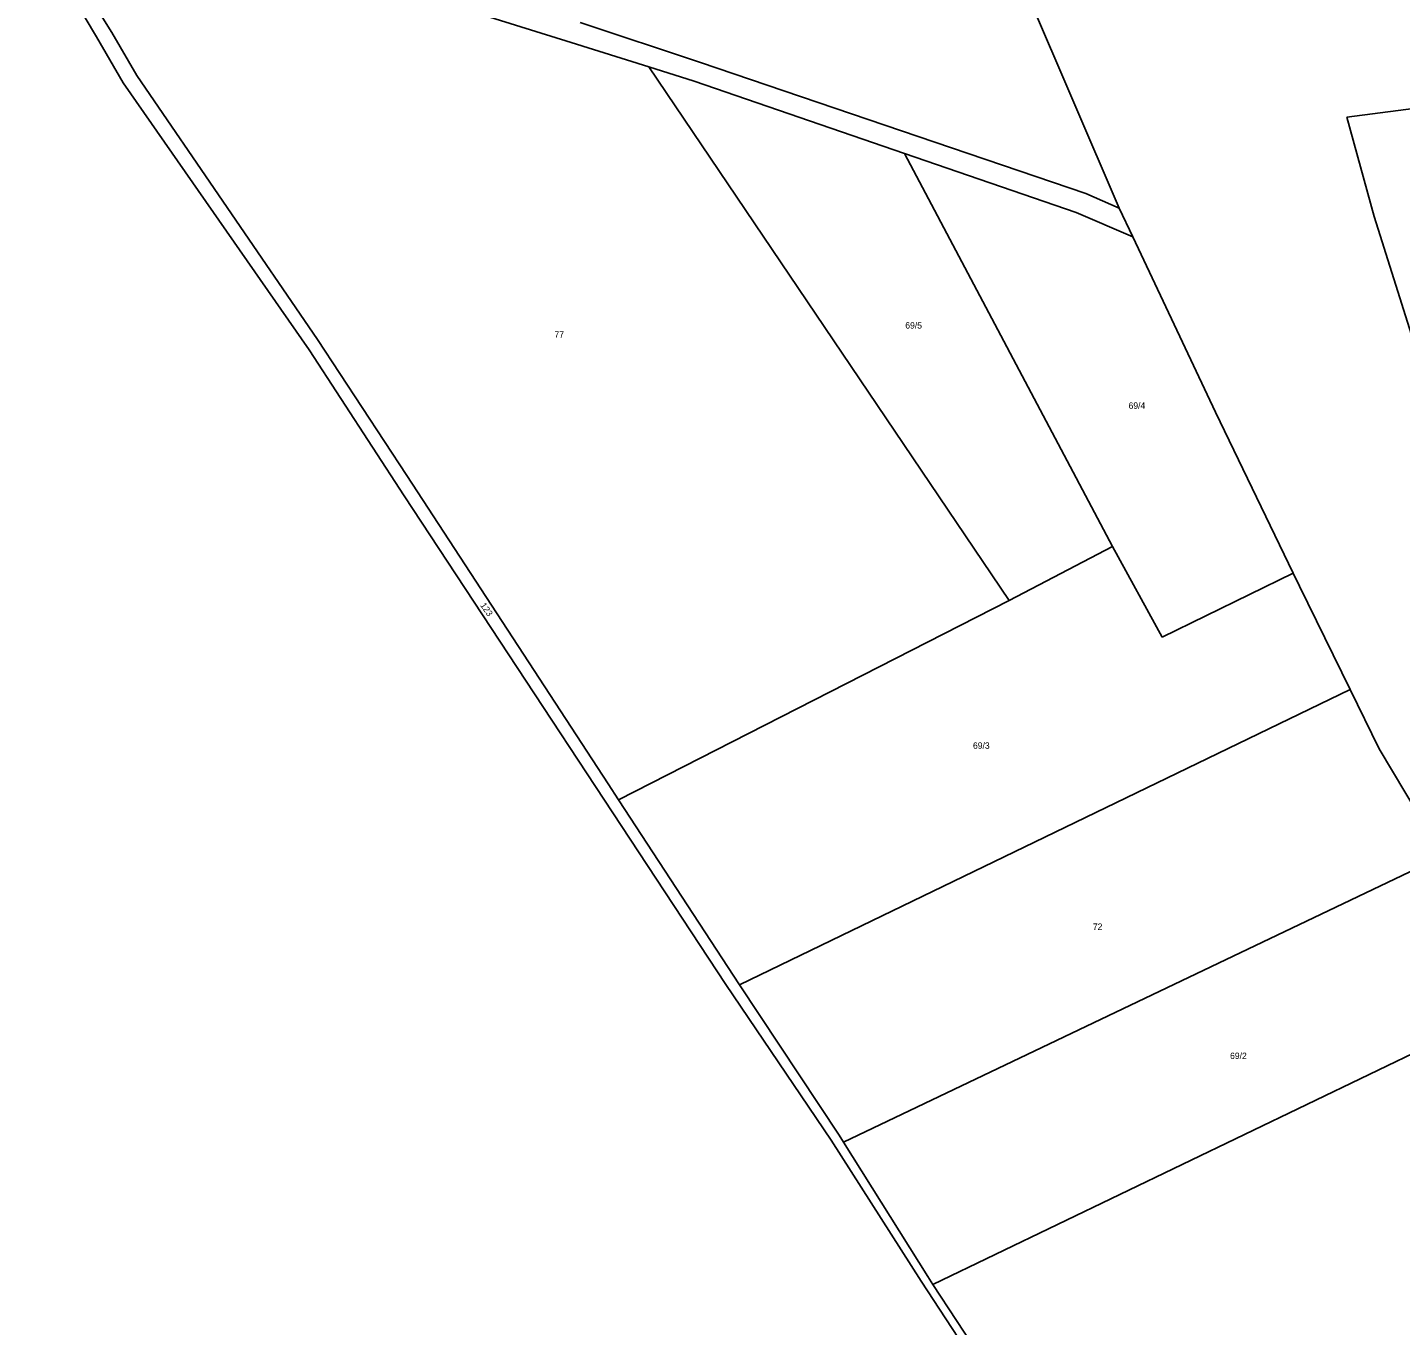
# Model space of a CAD drawing. Extents: x -752343 to -750336, y -1035826 to -1033329.
# Drawn here: x -750977.4 to -750613.5, y -1035442.9 to -1035099 of the extents above; entities that cross this region are included whole.
import ezdxf

# ---------------------------------------------------------------- set-up
doc = ezdxf.new("R2010")
doc.units = 0
doc.layers.add('KN_HRANICE', color=7, linetype='Continuous')
doc.layers.add('KN_PARCELY', color=7, linetype='Continuous')

msp = doc.modelspace()

# ---------------------------------------------------------------- linework, layer by layer
at = {"layer": 'KN_HRANICE'}
for p, q in [((-750977.4, -1035070.62), (-750959.13, -1035101.47)), ((-750974.34, -1035069.13), (-750955.05, -1035100.37)), ((-750892.88, -1035084.41), (-750833.35, -1035102.98)), ((-750713.44, -1035087.79), (-750688.06, -1035146.89)), ((-750830.94, -1035097.68), (-750799.07, -1035108.28)), ((-750955.05, -1035100.37), (-750948.45, -1035111.72)), ((-750959.13, -1035101.47), (-750952.01, -1035113.65)), ((-750833.35, -1035102.98), (-750812.7, -1035109.45)), ((-750799.07, -1035108.28), (-750696.95, -1035143.05)), ((-750948.45, -1035111.72), (-750900.52, -1035181.7)), ((-750717.21, -1035250.8), (-750812.7, -1035109.45)), ((-750812.7, -1035109.45), (-750800.69, -1035113.22)), ((-750952.01, -1035113.65), (-750902.74, -1035184.42)), ((-750744.96, -1035132.4), (-750800.69, -1035113.22)), ((-750627.75, -1035122.82), (-750580.87, -1035116.68)), ((-750620.53, -1035149.1), (-750627.75, -1035122.82)), ((-750689.89, -1035236.52), (-750744.96, -1035132.4)), ((-750699.48, -1035148.05), (-750744.96, -1035132.4)), ((-750696.95, -1035143.05), (-750688.06, -1035146.89)), ((-750684.47, -1035154.53), (-750699.48, -1035148.05)), ((-750688.06, -1035146.89), (-750684.47, -1035154.53)), ((-750610.6, -1035180.44), (-750620.53, -1035149.1)), ((-750684.47, -1035154.53), (-750662.59, -1035200.92)), ((-750902.74, -1035184.42), (-750877.61, -1035223.09)), ((-750900.52, -1035181.7), (-750876.9, -1035217.73)), ((-750662.59, -1035200.92), (-750641.95, -1035243.61)), ((-750876.9, -1035217.73), (-750823.55, -1035299.39)), ((-750877.61, -1035223.09), (-750792.36, -1035352.54)), ((-750689.89, -1035236.52), (-750717.21, -1035250.8)), ((-750676.68, -1035260.56), (-750689.89, -1035236.52)), ((-750641.95, -1035243.61), (-750676.68, -1035260.56)), ((-750641.95, -1035243.61), (-750640.28, -1035247.07)), ((-750640.28, -1035247.07), (-750626.88, -1035274.39)), ((-750717.21, -1035250.8), (-750820.76, -1035303.65)), ((-750626.88, -1035274.39), (-750788.73, -1035352.67)), ((-750626.88, -1035274.39), (-750619.19, -1035290.09)), ((-750619.19, -1035290.09), (-750602.3, -1035318.55)), ((-750823.55, -1035299.39), (-750820.76, -1035303.65)), ((-750820.76, -1035303.65), (-750788.73, -1035352.67)), ((-750761.16, -1035394.35), (-750602.3, -1035318.55)), ((-750553.02, -1035343.26), (-750737.45, -1035432.01)), ((-750792.36, -1035352.54), (-750764.38, -1035393.81)), ((-750788.73, -1035352.67), (-750762.33, -1035392.48)), ((-750764.38, -1035393.81), (-750740.57, -1035431.12)), ((-750762.33, -1035392.48), (-750761.16, -1035394.35)), ((-750761.16, -1035394.35), (-750738.8, -1035429.95)), ((-750740.57, -1035431.12), (-750710.58, -1035476.86)), ((-750738.8, -1035429.95), (-750737.45, -1035432.01)), ((-750737.45, -1035432.01), (-750708.72, -1035475.83))]:
    msp.add_line(p, q, dxfattribs=at)

# ---------------------------------------------------------------- texts
at = {"layer": 'KN_PARCELY'}
for s, p in [('69/5', (-750744.78, -1035178.8)), ('77', (-750837.74, -1035181.21)), ('69/4', (-750685.61, -1035200.05)), ('69/3', (-750726.84, -1035290.12)), ('72', (-750695.07, -1035338.1)), ('69/2', (-750658.71, -1035372.31))]:
    msp.add_text(s, height=1.7, dxfattribs=at).set_placement(p)
msp.add_text('123', height=1.7, rotation=304.642, dxfattribs=at).set_placement((-750857.5, -1035252.12))

doc.saveas('drawing.dxf')
